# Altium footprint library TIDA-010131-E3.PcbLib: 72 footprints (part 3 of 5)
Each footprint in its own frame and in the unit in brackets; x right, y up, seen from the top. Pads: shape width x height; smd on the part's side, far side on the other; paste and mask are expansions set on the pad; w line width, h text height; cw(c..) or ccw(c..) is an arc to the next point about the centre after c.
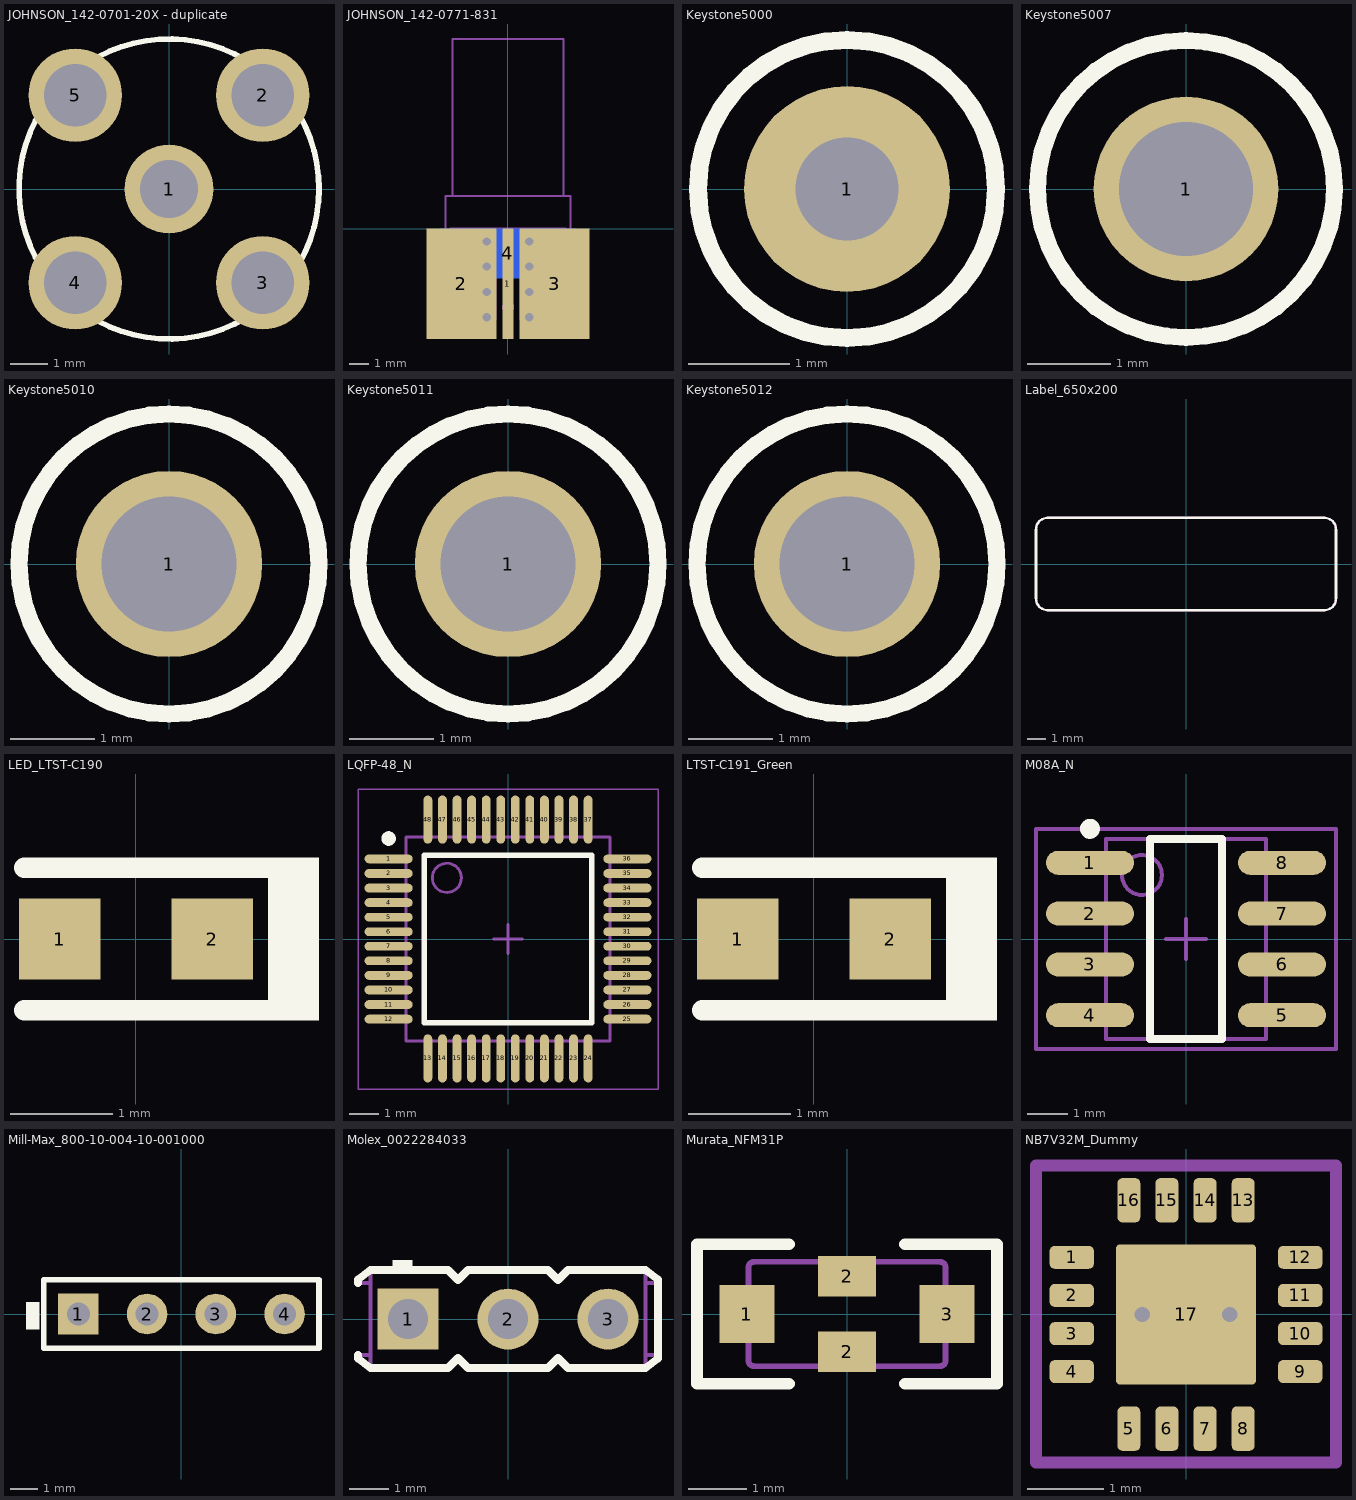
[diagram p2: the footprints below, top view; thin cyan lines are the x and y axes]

## JOHNSON_142-0701-20X - duplicate [mil]
pads (5):
  round 95 hole 62: 1(0,0)
  round 100 hole 67: 2(100,100) 3(100,-100) 4(-100,-100) 5(-100,100)
Top Overlay:
  circle w6: c0,0 r160
Mechanical 5:
  circle w5: c0,0 r160
  text ".Designator" at 36.58,6.45 h25
3D body "Emerson_142-0701-201.stp": height 375, standoff -155, extent -155.99,-155.8 156.01,155.8

## JOHNSON_142-0771-831 [mil] "JACK, SMA, 50 Ohm, Gold, Edge Mount"
height 123.5
pads (12):
  rect 22x218 smd: 1(0,-109)
  rect 138.25x218 smd: 2(-92.12,-109) 3(92.13,-109)
  rect 270x97.5 smd far side: 4(0,-48.75)
  round 16 hole 16: ""(-42,-175) ""(-42,-125) ""(-42,-75) ""(-42,-25) ""(42,-175) ""(42,-125) ""(42,-75) ""(42,-25)
Mechanical 5:
  circle w3.94: c0,-155 r10
  lines w3.94: -110,65 -110,375 110,375 110,65 ; -79.36,0 -79.36,-179 ; -25,-65 25,-65 ; -25,-60 25,-60 ; -25,0 -25,-179 -79.36,-179 ; -7.5,0 -7.5,-22.5 ccw(c0,-22.5) 7.5,-22.5 7.5,0 ; 25,0 25,-179 79.36,-179 ; 79.36,0 79.36,-179 ; -114.35,-179 -79.36,-179 ; -114.35,-179 -114.35,0 114.34,0 114.34,-179 ; -114.35,-179 -123.5,-179 -123.5,65 123.5,65 123.5,-179 114.34,-179 ; 79.36,-179 114.34,-179
  text ".Designator" at -175,-210 h25
3D body "142-0771-831.stp": height 130.9, standoff -116, extent -123.5,-179 123.47,375

## Keystone5000 [mil] "For Keystone 500x miniature loop terminals"
height 181.1
pads (1):
  round 80 hole 40: 1(0,0)
Top Overlay:
  circle w7: c0,0 r58
Mechanical 5:
  circle w5: c0,0 r58.31
  text ".Designator" at -14,47.2 h25
3D body "Keystone_5000.stp": height 181.97, standoff -118.11, extent -49,-49 49.04,49.24

## Keystone5007 [mil] "Keystone Compact loops"
height 220
pads (1):
  round 87 hole 63: 1(0,0)
Top Overlay:
  circle w7.99: c0,0 r70
Mechanical 5:
  circle w5: c0,0 r70.71
  text ".Designator" at -55,-15 h25
3D body "Keystone_5007.stp": height 225.2, standoff -129.92, extent -63,-63 62.49,62.74

## Keystone5010 [mil] "Keystone Multipurpose loops"
height 320
pads (1):
  round 87 hole 63: 1(0,0)
Top Overlay:
  circle w7.99: c0,0 r70
Mechanical 5:
  circle w5: c0,0 r69.46
  text ".Designator" at 28.5,14.4 h25
3D body "Keystone_5010.stp": height 318.9, standoff -125.98, extent -63,-63 62.74,62.49

## Keystone5011 [mil] "Keystone Multipurpose loops"
height 320
pads (1):
  round 87 hole 63: 1(0,0)
Top Overlay:
  circle w7.99: c0,0 r70
Mechanical 5:
  circle w5: c0,0 r69.46
  text ".Designator" at 9.51,-35.02 h25
3D body "Keystone_5011.stp": height 318.9, standoff -125.98, extent -63,-63 62.74,62.49

## Keystone5012 [mil] "Keystone Multipurpose loops"
height 320
pads (1):
  round 87 hole 63: 1(0,0)
Top Overlay:
  circle w7.99: c0,0 r70
Mechanical 5:
  circle w5: c0,0 r69.46
  text ".Designator" at 37.32,14.4 h25
3D body "Keystone_5012.stp": height 318.9, standoff -125.98, extent -63,-63 62.74,62.49

## Label_650x200 [mil] "Thermal Transfer Label"
height 1
pads (1):
  round 1 on Mech13: 0(0,0)
Top Overlay:
  lines w5: -325,-75 ccw(c-300,-75) -300,-100 ; -325,75 cw(c-300,75) -300,100 ; 300,-100 ccw(c300,-75) 325,-75 ; 300,100 cw(c300,75) 325,75
  lines w6: -325,-75 -325,75 ; -300,-100 300,-100 ; -300,100 300,100 ; 325,-75 325,75
Mechanical 5:
  lines w5: -325,-75 ccw(c-300,-75) -300,-100 300,-100 ccw(c300,-75) 325,-75 325,75 ccw(c300,75) 300,100 -300,100 ccw(c-300,75) -325,75 -325,-75
  text ".Designator" at -60,-20 h25
3D body: height 1, standoff 0, extent -325.02,-100.02 325.02,100.02

## LED_LTST-C190 [mm] "Lite-On"
height 0.9
pads (2):
  rect 0.8x0.8 smd: 1(-0.75,0) 2(0.75,0)
Top Overlay:
  region: 1.8,0.8 1.3,0.8 1.3,-0.8 1.8,-0.8
  lines w0.2: -1.1,-0.7 1.4,-0.7 ; -1.1,0.7 1.4,0.7
Mechanical 5:
  region: 1.8,0.75 1.3,0.75 1.3,-0.75 1.8,-0.75
  lines w0.1: -1.1,-0.7 1.4,-0.7 ; -1.1,0.7 1.4,0.7
  text ".Designator" at 0.292,-0.384 h0.51
3D body "Lite-On_LTST_C190.stp": height 0.9, standoff 0, extent -0.85,-0.45 0.85,0.45

## LQFP-48_N [mm] "QFP, 48-Leads, Body 7x7mm, Pitch 0.5mm, IPC Medium Density"
height 1.6
pads (48):
  oval 1.65x0.3 smd: 1(-4.1,2.75) 2(-4.1,2.25) 3(-4.1,1.75) 4(-4.1,1.25) 5(-4.1,0.75) 6(-4.1,0.25) 7(-4.1,-0.25) 8(-4.1,-0.75) 9(-4.1,-1.25) 10(-4.1,-1.75) 11(-4.1,-2.25) 12(-4.1,-2.75) 25(4.1,-2.75) 26(4.1,-2.25) 27(4.1,-1.75) 28(4.1,-1.25) 29(4.1,-0.75) 30(4.1,-0.25) 31(4.1,0.25) 32(4.1,0.75) 33(4.1,1.25) 34(4.1,1.75) 35(4.1,2.25) 36(4.1,2.75)
  oval 0.3x1.65 smd: 13(-2.75,-4.1) 14(-2.25,-4.1) 15(-1.75,-4.1) 16(-1.25,-4.1) 17(-0.75,-4.1) 18(-0.25,-4.1) 19(0.25,-4.1) 20(0.75,-4.1) 21(1.25,-4.1) 22(1.75,-4.1) 23(2.25,-4.1) 24(2.75,-4.1) 37(2.75,4.1) 38(2.25,4.1) 39(1.75,4.1) 40(1.25,4.1) 41(0.75,4.1) 42(0.25,4.1) 43(-0.25,4.1) 44(-0.75,4.1) 45(-1.25,4.1) 46(-1.75,4.1) 47(-2.25,4.1) 48(-2.75,4.1)
Top Overlay:
  circle w0.25: c-4.1,3.45 r0.125
  lines w0.2: -2.875,-2.875 2.875,-2.875 2.875,2.875 -2.875,2.875 -2.875,-2.875
Mechanical 5:
  circle w0.1: c-2.1,2.1 r0.5
  lines w0.1: -3.5,-3.5 -3.5,3.5 3.5,3.5 3.5,-3.5 -3.5,-3.5
Mechanical 15:
  lines w0.05: -5.15,-5.15 5.15,-5.15 5.15,5.15 -5.15,5.15 -5.15,-5.15
  lines w0.1: -0.5,0 0.5,0 ; 0,-0.5 0,0.5
3D body: height 1.61, standoff 0, extent -2.599,1.601 -1.6,2.6
3D body: height 1.6, standoff 0.05, extent -3.5,-3.5 3.5,3.5

## LTST-C191_Green [mm] "Lite-On"
height 0.65
pads (2):
  rect 0.8x0.8 smd: 1(-0.75,0) 2(0.75,0)
Top Overlay:
  region: 1.8,0.8 1.3,0.8 1.3,-0.8 1.8,-0.8
  lines w0.2: -1.1,-0.7 1.4,-0.7 ; -1.1,0.7 1.4,0.7
Mechanical 5:
  region: 1.8,0.75 1.3,0.75 1.3,-0.75 1.8,-0.75
  lines w0.1: -1.1,-0.7 1.4,-0.7 ; -1.1,0.7 1.4,0.7
  text ".Designator" at 0.629,0.247 h0.64
3D body: height 0.2, standoff 0, extent -0.849,-0.449 0.849,0.449
3D body: height 0.65, standoff 0.2, extent -0.624,-0.449 0.624,0.449

## M08A_N [mm] "SOIC, 8-Leads, Body 4.9x3.9mm, Pitch 1.27mm, IPC Medium Density"
height 1.75
pads (8):
  oval 2.2x0.6 smd: 1(-2.4,1.905) 2(-2.4,0.635) 3(-2.4,-0.635) 4(-2.4,-1.905) 5(2.4,-1.905) 6(2.4,-0.635) 7(2.4,0.635) 8(2.4,1.905)
Top Overlay:
  circle w0.25: c-2.4,2.755 r0.125
  lines w0.2: -0.9,-2.5 0.9,-2.5 0.9,2.5 -0.9,2.5 -0.9,-2.5
Mechanical 5:
  text ".Designator" at -0.928,2.867 h0.64
Mechanical 13:
  circle w0.1: c-1.1,1.6 r0.5
  lines w0.1: -2,-2.5 2,-2.5 2,2.5 -2,2.5 -2,-2.5
Mechanical 15:
  lines w0.1: -0.5,0 0.5,0 ; 0,-0.5 0,0.5 ; -3.75,-2.75 3.75,-2.75 3.75,2.75 -3.75,2.75 -3.75,-2.75
3D body: height 1.75, standoff 0, extent -2,-2.5 2,2.5

## Mill-Max_800-10-004-10-001000 [mm] "Mill-Max"
height 8.128
pads (4):
  rect 1.5x1.5 hole 0.85: 1(-3.81,0)
  round 1.5 hole 0.85: 2(-1.27,0) 3(1.27,0) 4(3.81,0)
Top Overlay:
  region: -5.238,-0.571 -5.238,0.445 -5.746,0.445 -5.746,-0.571
  lines w0.203: -5.08,-1.27 -5.08,1.27 5.08,1.27 5.08,-1.27 -5.08,-1.27
Mechanical 5:
  lines w0.102: -5.08,-1.27 5.08,-1.27 5.08,1.27 -5.08,1.27 -5.08,-1.27
  text ".Designator" at 0.359,-0.838 h0.64
3D body: height 0.81, standoff -3, extent -4.112,-0.304 -3.505,0.304
3D body: height 0.81, standoff -3, extent -1.572,-0.304 -0.965,0.304
3D body: height 0.81, standoff -3, extent 0.968,-0.304 1.575,0.304
3D body: height 0.81, standoff -3, extent 3.508,-0.304 4.115,0.304
3D body: height 8.13, standoff 0, extent -4.188,-0.38 -3.429,0.38
3D body: height 8.13, standoff 0, extent -1.648,-0.38 -0.889,0.38
3D body: height 8.13, standoff 0, extent 0.892,-0.38 1.651,0.38
3D body: height 8.13, standoff 0, extent 3.432,-0.38 4.191,0.38
3D body: height 3.17, standoff 0, extent -5.079,-1.269 5.079,1.269

## Molex_0022284033 [mm] "Header, 2.54mm, 3x1, TH"
height 8.88
pads (3):
  rect 1.55x1.55 hole 1.02: 1(-2.54,0)
  round 1.55 hole 1.02: 2(0,0) 3(2.54,0)
Top Overlay:
  rectangle: -2.93,1.245 -2.43,1.5
  lines w0.2: -3.81,-0.914 -3.81,-1.003 -3.492,-1.245 -1.524,-1.245 -1.27,-0.991 -1.016,-1.245 1.016,-1.245 1.27,-0.991 1.524,-1.245 3.492,-1.245 3.81,-1.003 3.81,-0.914 3.81,0.914 3.81,1.003 3.492,1.245 1.524,1.245 1.27,0.991 1.016,1.245 -1.016,1.245 -1.27,0.991 -1.524,1.245 -3.492,1.245 -3.81,1.003 -3.81,0.914
Mechanical 5:
  lines w0.1: -3.492,-1.168 -3.492,1.168 ; -3.492,-0.914 -3.81,-0.914 -3.81,-1.003 -3.492,-1.245 -1.524,-1.245 -1.27,-0.991 -1.016,-1.245 1.016,-1.245 1.27,-0.991 1.524,-1.245 3.492,-1.245 3.81,-1.003 3.81,-0.914 ; -3.492,0.914 -3.81,0.914 -3.81,1.003 -3.492,1.245 -1.524,1.245 -1.27,0.991 -1.016,1.245 1.016,1.245 1.27,0.991 1.524,1.245 3.492,1.245 3.81,1.003 3.81,0.914 ; 3.492,-1.168 3.492,1.168 ; 3.492,-0.914 3.81,-0.914 ; 3.492,0.914 3.81,0.914 ; 3.81,-0.914 3.81,0.914
  text ".Designator" at -1.021,-0.458 h0.64
3D body "022284033.stp": height 8.4, standoff -3.16, extent -3.81,-1.244 3.81,1.245

## Murata_NFM31P [mm] "SMD, 3-Leads, Body 3.2x1.6mm"
height 1.5
pads (4):
  rect 0.95x1 smd paste-2 mask-2: 1(-1.725,0) 3(1.725,0)
  rect 1x0.7 smd paste-2 mask+0: 2(0,-0.65) 2(0,0.65)
Top Overlay:
  lines w0.2: -1,-1.2 -2.586,-1.2 -2.586,1.2 -1,1.2 ; 1,-1.2 2.586,-1.2 2.586,1.2 1,1.2
Top Paste:
  rectangle: -0.5,0.3 0.5,1.3
  region: 0.5,-0.3 -0.5,-0.3 -0.5,-1.3 0.5,-1.3
  rectangle: 1.25,-0.6 2.2,0.6
  region: -1.25,0.6 -2.2,0.6 -2.2,-0.6 -1.25,-0.6
Top Solder:
  region: -0.7,1 -2.2,1 -2.2,-1 -0.7,-1
  rectangle: 0.7,-1 2.2,1
Mechanical 5:
  lines w0.1: -1.7,-0.8 ccw(c-1.6,-0.8) -1.6,-0.9 1.6,-0.9 ccw(c1.6,-0.8) 1.7,-0.8 1.7,0.8 ccw(c1.6,0.8) 1.6,0.9 -1.6,0.9 ccw(c-1.6,0.8) -1.7,0.8 -1.7,-0.8
  text ".Designator" at 0.695,0.097 h0.64
3D body "NFM31PC276B0J3L.stp": height 1.5, standoff 0, extent -1.7,-0.9 1.7,0.9

## NB7V32M_Dummy [mm]
pads (17):
  rrect42% 0.58x0.3 smd mask+0.051: 1(-1.499,0.75) 2(-1.499,0.25) 3(-1.499,-0.25) 4(-1.499,-0.75) 9(1.499,-0.75) 10(1.499,-0.25) 11(1.499,0.25) 12(1.499,0.75)
  rrect42% 0.3x0.58 smd mask+0.051: 5(-0.75,-1.499) 6(-0.25,-1.499) 7(0.25,-1.499) 8(0.75,-1.499) 13(0.75,1.499) 14(0.25,1.499) 15(-0.25,1.499) 16(-0.75,1.499)
  rrect6% 1.84x1.84 smd paste-0.825: 17(0,0)
via 0.575,0 diameter 0.5 hole 0.2
via -0.575,0 diameter 0.5 hole 0.2
Mechanical 5:
  lines w0.152: -1.968,-1.943 1.968,-1.943 1.968,1.956 0,1.956 -1.968,1.956 -1.968,-1.943
  text ".Designator" at 0,-0.064 h0.64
